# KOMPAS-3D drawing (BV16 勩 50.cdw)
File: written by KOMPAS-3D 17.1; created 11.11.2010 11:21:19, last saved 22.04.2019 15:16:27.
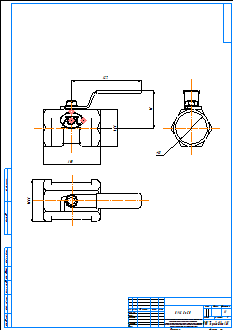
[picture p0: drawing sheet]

Sheet 1: A2, portrait

Title block, sheet 1: name: BV16 Ду 50; material: Внимание! Данный продукт является объектом авторского права ООО «Торговый Дом АДЛ». / Запрещается изменение, копирование, распространение / (в том числе путем копирования на другие сайты и ресурсы в Интернете) / или любое иное использование информации и объектов без предварительного / согласия правообладателя (ООО «Торговый Дом АДЛ»).; scale: 1:1; sheets: 1; organisation: ООО "Торговый дом АДЛ"; sheet format: A2; stored path: \\adlc.lan\data\АДЛ_ПКД\3D-модели\ADL production\Краны шаровые серии BV\BV16\KOMPAS 2D\BV16 Ду 50.cdw

Views: Спереди 1, Проекционный вид 2, Проекционный вид 3
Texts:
  user
  adl
Dimensions and other numbers on the sheet: 65,2; 100; 75; 127; 58; 75,28; 1:1; 1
